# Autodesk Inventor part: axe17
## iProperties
Shininess: 86.0
Compacted: True
Length Units: 11269
Angle Units: 11279
Time Units: 11290
Mass Units: 11283
Length Display Precision: 3
Angle Display Precision: 2
Created: 2001-12
Part Number: axe17
Material: Par défaut
Document SubType Name: Modélisation
Designer: pichon
Density: 0.0
Volumn: 0.0
Area: 0.0
PropertySet Name: Model Information
Control State: 0
Master: False
Checked Out: False
Author: pichon
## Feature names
1. Révolution1 [Revolution]
2. Révolution2 [Revolution]
3. Symétrie1 [Mirror]
